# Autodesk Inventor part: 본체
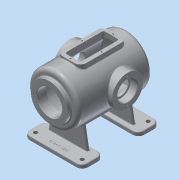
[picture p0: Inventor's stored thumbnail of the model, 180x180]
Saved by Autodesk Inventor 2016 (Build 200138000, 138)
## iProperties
Created: 2016-02
Part Number: 본체
Material: 알루미늄 6061
Document SubType Name: Modeling
Designer: mduedu
Density: 2.71 g/cm^3
Appearance: 알루미늄 - 평지
Mass: 3305.58 g
Surface Area: 2487 cm^2
Volume: 1219.77 cm^3
Author: mduedu
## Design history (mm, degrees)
sketch "스케치2"
  geometry: L1 (0, 100)-(0, -100); L2 (65, -87.083)-(65, 100); L3 (65, 100)-(0, 100); A1 r 170 centre (0, 70) between (0, -100) and (65, -87.083); 2 further points
  constraints: 6 end point, 2 point on circle, 1 centre point, 1 coincident, 1 horizontal, 1 midpoint, 1 parallel, 1 point on line, 1 vertical
  dimensions: "d3" = 200 distance of L1.start L1.end; "d5" = 130 diameter of L2 L1; "d6" = 170 radius of A1
revolve "회전1" sketch "스케치2" stored, may be unused: angle "d7" = 90 deg
sketch "스케치3"
  geometry: C1 r 47.5 at (0, 0); 1 further point
  constraints: 1 centre point, 1 coincident
  dimensions: "d8" = 95 diameter of C1
extrude "돌출2" join sketch "스케치3" distance "d10" = 10; taper "d11" = 0 deg
sketch "스케치5"
  geometry: L1 (47.5, 110)-(47.5, 100) reference; L2 (47.5, 100)-(65, 100) reference; L3 (65, 100)-(65, -87.083) reference; L4 (-65, -87.083)-(-65, 100) reference; L5 (-65, 100)-(-47.5, 100) reference; L6 (-47.5, 100)-(-47.5, 110) reference; L7 (-47.5, 110)-(47.5, 110) reference; L8 (55, 85)-(55, -80.25); L9 (0, 85)-(55, 85); L10 (0, 85)-(0, -90); A1 r 170 centre (0, 70) between (-65, -87.083) and (0, -100) reference; A2 r 170 centre (0, 70) between (0, -100) and (65, -87.083) reference; A3 r 160 centre (0, 70) between (0, -90) and (55, -80.25); 1 further point
  constraints: 6 end point, 2 point on circle, 1 centre point, 1 parallel, 1 perpendicular, 1 point on line, 1 vertical
  dimensions: "d13" = 10 distance between parallel lines of L3 L8; "d14" = 10 radial gap between concentric circles of A3 A1; "d15" = 15 distance between parallel lines of L9 L2
revolve "회전2" sketch "스케치5" stored, may be unused: angle "d16" = 90 deg
hole "구멍1" diameter "d19" = 65; stored, may be unused: countersink angle "d23" = 90 deg, drill point angle "d25" = 118 deg; dims "d17" = 10, "d18" = 10, "d20" = 6, "d21" = 4, "d22" = 2, "d24" = 8
node "작업 평면1"
sketch "스케치6"
  geometry: L1 (47.5, 110)-(-47.5, 110) reference; C1 r 40 at (0, -17); 1 further point
  constraints: 1 centre point, 1 vertical alignment
  dimensions: "d27" = 80 diameter of C1; "d29" = 127 distance from line of C1.centre L1
extrude "돌출3" join sketch "스케치6" stored distance "d30" = 10; taper "d31" = 0 deg
hole "구멍2" diameter "d34" = 42; stored, may be unused: countersink angle "d38" = 90 deg, drill point angle "d40" = 118 deg; dims "d32" = 10, "d33" = 10, "d35" = 6, "d36" = 52, "d37" = 18, "d39" = 8
sketch "스케치7" dims "d41" = 65
  geometry: C1 r 40 at (0, 0) reference; 3 further points
  constraints: 2 vertical alignment, 1 coincident, 2 other
hole "구멍3" sketch "스케치7" at (0, 32.5) diameter "d43" = 3.242; stored, may be unused: countersink angle "d47" = 90 deg, drill point angle "d49" = 118 deg; dims "d44" = 11, "d45" = 13, "d46" = 18, "d48" = 13
sketch "스케치8" dims "d53" = 80
  geometry: 3 further points
  constraints: 2 vertical alignment, 1 coincident, 2 other
hole "구멍4" sketch "스케치8" at (0, 40) diameter "d56" = 3.242; stored, may be unused: countersink angle "d60" = 90 deg, drill point angle "d62" = 118 deg; dims "d57" = 11, "d58" = 13, "d59" = 18, "d61" = 13
fillet "모깎기1" dims "d66" = 10
fillet "모깎기2" dims "d67" = 3
fillet "모깎기3" dims "d68" = 0.3
chamfer "모따기1" distance "d69" = 1; stored, may be unused: second distance "d70" = 2, angle "d71" = 45 deg
node "작업 평면2"
sketch "스케치9"
  geometry: L1 (75, 100)-(-75, 100); L2 (-75, 100)-(-75, -100); L3 (-75, -100)-(75, -100); L4 (75, -100)-(75, 100); 1 further point
  constraints: 8 end point, 2 parallel, 1 horizontal, 1 perpendicular
  dimensions: "d73" = 200 distance of L3.end L1.start; "d75" = 150 distance of L2.end L3.end; "d76" = 100 distance from line of L1 point (0, 0); "d77" = 75 distance from line of L4 point (0, 0)
extrude "돌출4" join sketch "스케치9" distance "d78" = 10; taper "d79" = 0 deg
sketch "스케치10"
  geometry: L1 (-75, -100)-(75, -100) reference; L2 (75, 100)-(-75, 100) reference; L3 (0, -100)-(0, 100); L4 (-75, 100)-(-75, -100) reference; L5 (75, -100)-(75, 100) reference; L6 (-75, 0)-(75, 0); L7 (-50, -63)-(50, -63); L8 (50, -63)-(50, -55); L9 (50, -55)-(-50, -55); L10 (-50, -55)-(-50, -63); L11 (-50, 63)-(50, 63); L12 (50, 63)-(50, 55); L13 (50, 55)-(-50, 55); L14 (-50, 55)-(-50, 63); 1 further point
  constraints: 20 end point, 4 midpoint, 4 symmetric about line, 2 parallel, 1 horizontal, 1 perpendicular, 1 other
  dimensions: "d80" = 8 distance of L9.end L7.start; "d82" = 100 distance of L7.start L7.end; "d83" = 55 distance between parallel lines of L9 L6
extrude "돌출5" join sketch "스케치10" stored distance "d84" = 10; taper "d85" = 0 deg
feature "면 기울기1" dims angle "d86" = 10 deg
sketch "스케치11"
  geometry: L1 (-110, 55)-(-51.482, 55) reference; L2 (-110, -55)-(-51.482, -55) reference; L3 (-95, 55)-(-95, -55); L4 (-65, 90)-(-65, -80.25) reference; 1 further point
  constraints: 2 end point, 2 point on line, 1 perpendicular
  dimensions: "d87" = 30 distance between parallel lines of L3 L4
feature "리브1" sketch "스케치11" dims "d88" = 1, "d89" = 8, "d90" = 0, "d91" = 0, "d92" = 1, "d93" = 1
sketch "스케치12"
  geometry: L1 (-110, 55)-(-51.482, 55) reference; L2 (-110, -55)-(-51.482, -55) reference; L3 (-110, 100)-(-110, -100) reference; L4 (-120, 152)-(-120, -142) reference; L5 (-110, 45)-(-120, 45); L6 (-120, 45)-(-120, -45); L7 (-120, -45)-(-110, -45); L8 (-110, -45)-(-110, 45); 1 further point
  constraints: 8 end point, 2 parallel, 2 point on line, 1 horizontal, 1 perpendicular
  dimensions: "d94" = 10 distance between parallel lines of L7 L2; "d95" = 10 distance between parallel lines of L1 L5
extrude "돌출6" cut sketch "스케치12" stored distance "d96" = 10; taper "d97" = 0 deg
fillet "모깎기4" dims "d98" = 15
sketch "스케치13"
  geometry: C1 r 5 at (-60, -85); C2 r 5 at (60, -85); C3 r 5 at (60, 85); C4 r 5 at (-60, 85); A1 r 15 centre (-60, -85) between (-75, -85) and (-60, -100) reference; A2 r 15 centre (60, -85) between (60, -100) and (75, -85) reference; A3 r 15 centre (60, 85) between (75, 85) and (60, 100) reference; A4 r 15 centre (-60, 85) between (-60, 100) and (-75, 85) reference; 1 further point
  constraints: 4 centre point, 4 coincident, 3 equal radius
  dimensions: "d99" = 10 diameter of C1
extrude "돌출7" cut sketch "스케치13" stored distance "d101" = 10; taper "d102" = 0 deg
fillet "모깎기5" dims "d103" = 3, "d104" = 3
fillet "모깎기6" dims "d105" = 3
sketch "스케치14"
  geometry: L1 (-60, -100)-(60, -100) reference; 2 further points
  constraints: 1 vertical alignment, 1 other
  dimensions: "d106" = 15 distance from line of point (0, -85) L1
feature "엠보싱1" sketch "스케치14" dims "d3" = 200, "d5" = 130, "d6" = 170, "d14" = 10, "d107" = 0.5, "d108" = 0
node "작업 평면3"
sketch "스케치15"
  geometry: L1 (-30, 60)-(30, 60); L2 (30, 60)-(30, -60); L3 (30, -60)-(-30, -60); L4 (-30, -60)-(-30, 60); 2 further points
  constraints: 8 end point, 2 parallel, 1 horizontal, 1 midpoint, 1 perpendicular, 1 vertical alignment
  dimensions: "d110" = 60 distance of L2.end L3.end; "d112" = 60 distance from line of L3 point (0, 0); "d113" = 120 distance of L1.end L2.end
extrude "돌출8" join sketch "스케치15" stored distance "d114" = 10; taper "d115" = 0 deg
fillet "모깎기7" dims "d116" = 15
sketch "스케치16"
  geometry: L1 (-30, -45)-(-30, 45) reference; L2 (-15, 60)-(15, 60) reference; L3 (30, 45)-(30, -45) reference; L4 (15, -60)-(-15, -60) reference; L5 (15, 50)-(-15, 50); L6 (-20, 45)-(-20, -45); L7 (-15, -50)-(15, -50); L8 (20, -45)-(20, 45); A1 r 15 centre (-15, -45) between (-30, -45) and (-15, -60) reference; A2 r 15 centre (-15, 45) between (-15, 60) and (-30, 45) reference; A3 r 15 centre (15, 45) between (30, 45) and (15, 60) reference; A4 r 15 centre (15, -45) between (15, -60) and (30, -45) reference; A5 r 5 centre (-15, 45) between (-15, 50) and (-20, 45); A6 r 5 centre (-15, -45) between (-20, -45) and (-15, -50); A7 r 5 centre (15, -45) between (15, -50) and (20, -45); A8 r 5 centre (15, 45) between (20, 45) and (15, 50); 1 further point
  constraints: 8 end point, 8 point on circle, 4 centre point, 7 other
  dimensions: "d117" = 10 distance between parallel lines of L6 L1
extrude "돌출9" cut sketch "스케치16" stored distance "d118" = 10; taper "d119" = 0 deg
fillet "모깎기8" dims "d120" = 3
sketch "스케치17"
  geometry: L1 (-30, -45)-(-30, 45) reference; L2 (-15, 60)-(15, 60) reference; L3 (30, 45)-(30, -45) reference; L4 (15, -60)-(-15, -60) reference; L5 (20, -45)-(20, 45) reference; L6 (15, 50)-(-15, 50) reference; L7 (-20, 45)-(-20, -45) reference; L8 (-15, -50)-(15, -50) reference; L9 (15, 55)-(-15, 55); L10 (-25, 45)-(-25, -45); L11 (-15, -55)-(15, -55); L12 (25, -45)-(25, 45); A1 r 15 centre (-15, 45) between (-15, 60) and (-30, 45) reference; A2 r 15 centre (15, 45) between (30, 45) and (15, 60) reference; A3 r 15 centre (15, -45) between (15, -60) and (30, -45) reference; A4 r 15 centre (-15, -45) between (-30, -45) and (-15, -60) reference; A5 r 5 centre (15, -45) between (15, -50) and (20, -45) reference; A6 r 5 centre (15, 45) between (20, 45) and (15, 50) reference; A7 r 5 centre (-15, 45) between (-15, 50) and (-20, 45) reference; A8 r 5 centre (-15, -45) between (-20, -45) and (-15, -50) reference; A9 r 10 centre (-15, 45) between (-15, 55) and (-25, 45); A10 r 10 centre (-15, -45) between (-25, -45) and (-15, -55); A11 r 10 centre (15, -45) between (15, -55) and (25, -45); A12 r 10 centre (15, 45) between (25, 45) and (15, 55); 5 further points
  constraints: 8 end point, 8 point on circle, 4 centre point, 4 midpoint, 7 other
  dimensions: "d121" = 5 distance between parallel lines of L10 L1
hole "구멍5" sketch "스케치17" at (0, 55), (25, 0), (0, -55), (-25, 0) diameter "d122" = 3.242; stored, may be unused: countersink angle "d126" = 90 deg, drill point angle "d128" = 118 deg; dims "d123" = 9, "d124" = 13, "d125" = 18, "d127" = 11
fillet "모깎기9" dims "d129" = 3
node "솔리드2"
pattern_circular "원형 패턴1" dims angle "d51" = 360 deg
mirror "대칭1"
pattern_circular "원형 패턴2" dims angle "d64" = 360 deg
node "절단 모서리 투영1"
node "절단 모서리 투영2"
node "절단 모서리 투영3"
other parameters: "d26" = 75
